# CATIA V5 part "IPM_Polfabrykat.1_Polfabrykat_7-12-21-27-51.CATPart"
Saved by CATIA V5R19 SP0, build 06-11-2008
Part number: IPM_Polfabrykat.1_Polfabrykat7-12-21-27-51
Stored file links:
  G:\Catia\CD\Ustawienia\Ustawienia\IPM_Polfabrykat.1_Polfabrykat_7-12-21-27-51.CATPart
  G:\Catia\CD\Ustawienia\Ustawienia\Polfabrykat.CATPart
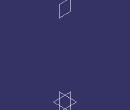
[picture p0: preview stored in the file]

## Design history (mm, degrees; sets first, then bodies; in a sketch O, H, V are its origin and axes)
Body1 (main body)
  Body2 "ImportedStock"
    Body3 "Polfabrykat"
      Solid1: linked copy from another document
    Add1: tool Body3
  Add2: tool Body2
  Body4 "Rough Turning.1"
    Plane1: stored without definition
    Sketch1 on Plane1, origin (0, 0, 38.2543), H (0, 0, 1), V (1, 0, 0)
      axis line L1 through (0, 0) direction (1, 0)
      line L2 (-0.5126, 0) -> (6.444, 4.0361)
      point P1 (-0.5126, 0)
      point P2 (6.444, 4.0361)
      line L3 (6.444, 4.0361) -> (6.6562, 4.2482)
      point P3 (6.444, 4.0361)
      point P4 (6.6562, 4.2482)
      arc A1 centre (6.3026, 4.6017) radius 0.5 from (6.6562, 4.2482) to (6.8007, 4.5582) ccw
      point P5 (6.6562, 4.2482)
      point P6 (6.8007, 4.5582)
      line L4 (6.8007, 4.5582) -> (7.5659, 13.304)
      point P7 (6.8007, 4.5582)
      point P8 (7.5659, 13.304)
      arc A2 centre (7.095, 13.3527) radius 0.4733 from (7.5659, 13.304) to (7.3556, 13.7478) ccw
      point P9 (7.5659, 13.304)
      point P10 (7.3556, 13.7478)
      line L5 (7.3556, 13.7478) -> (7.3556, 60.6354)
      point P11 (7.3556, 13.7478)
      point P12 (7.3556, 60.6354)
      arc A3 centre (6.8556, 60.6354) radius 0.5 from (7.3556, 60.6354) to (6.6056, 61.0684) ccw
      point P13 (7.3556, 60.6354)
      point P14 (6.6056, 61.0684)
      line L6 (6.6056, 61.0684) -> (-0.9974, 56.6788)
      point P15 (6.6056, 61.0684)
      point P16 (-0.9974, 56.6788)
      arc A4 centre (-0.7474, 56.2458) radius 0.5 from (-0.9974, 56.6788) to (-1.2455, 56.2894) ccw
      point P17 (-0.9974, 56.6788)
      point P18 (-1.2455, 56.2894)
      line L7 (-1.2455, 56.2894) -> (-2.0126, 47.5)
      point P19 (-1.2455, 56.2894)
      point P20 (-2.0126, 47.5)
      line L8 (-2.0126, 47.5) -> (-2.0126, 0)
      point P21 (-2.0126, 47.5)
      point P22 (-2.0126, 0)
      line L9 (-2.0126, 0) -> (-0.5126, 0)
      point P23 (-2.0126, 0)
      point P24 (-0.5126, 0)
      coincidence: P1 P24, P2 P3, P4 P5, P6 P7, P8 P9, P10 P11, P12 P13, P14 P15, P16 P17, P18 P19, P20 P21, P22 P23
    Shaft1: profile Sketch1, axis Sketch1.L1, angle 360
  Remove1: tool Body4
  Body5 "Rough Turning.2"
    Plane2: stored without definition
    Sketch2 on Plane2, origin (0, 0, 38.2543), H (0, 0, 1), V (1, 0, 0)
      axis line L1 through (0, 0) direction (1, 0)
      line L2 (0.5, 28.5858) -> (0.5, 45.5)
      point P1 (0.5, 28.5858)
      point P2 (0.5, 45.5)
      line L3 (0.5, 45.5) -> (-49.0126, 45.5)
      point P3 (0.5, 45.5)
      point P4 (-49.0126, 45.5)
      line L4 (-49.0126, 45.5) -> (-49.0126, 35.5071)
      point P5 (-49.0126, 45.5)
      point P6 (-49.0126, 35.5071)
      arc A1 centre (-48.5126, 35.5071) radius 0.5 from (-49.0126, 35.5071) to (-48.8661, 35.1536) ccw
      point P7 (-49.0126, 35.5071)
      point P8 (-48.8661, 35.1536)
      line L5 (-48.8661, 35.1536) -> (-48.859, 35.1464)
      point P9 (-48.8661, 35.1536)
      point P10 (-48.859, 35.1464)
      arc A2 centre (-48.5055, 35.5) radius 0.5 from (-48.859, 35.1464) to (-48.5055, 35) ccw
      point P11 (-48.859, 35.1464)
      point P12 (-48.5055, 35)
      line L6 (-48.5055, 35) -> (-44.0126, 35)
      point P13 (-48.5055, 35)
      point P14 (-44.0126, 35)
      line L7 (-44.0126, 35) -> (-44.0126, 30.5071)
      point P15 (-44.0126, 35)
      point P16 (-44.0126, 30.5071)
      arc A3 centre (-43.5126, 30.5071) radius 0.5 from (-44.0126, 30.5071) to (-43.8661, 30.1536) ccw
      point P17 (-44.0126, 30.5071)
      point P18 (-43.8661, 30.1536)
      line L8 (-43.8661, 30.1536) -> (-43.859, 30.1464)
      point P19 (-43.8661, 30.1536)
      point P20 (-43.859, 30.1464)
      arc A4 centre (-43.5055, 30.5) radius 0.5 from (-43.859, 30.1464) to (-43.5055, 30) ccw
      point P21 (-43.859, 30.1464)
      point P22 (-43.5055, 30)
      line L9 (-43.5055, 30) -> (-3.4268, 30)
      point P23 (-43.5055, 30)
      point P24 (-3.4268, 30)
      line L10 (-3.4268, 30) -> (-2.159, 28.7322)
      point P25 (-3.4268, 30)
      point P26 (-2.159, 28.7322)
      arc A5 centre (-1.8055, 29.0858) radius 0.5 from (-2.159, 28.7322) to (-1.8055, 28.5858) ccw
      point P27 (-2.159, 28.7322)
      point P28 (-1.8055, 28.5858)
      line L11 (-1.8055, 28.5858) -> (0.5, 28.5858)
      point P29 (-1.8055, 28.5858)
      point P30 (0.5, 28.5858)
      coincidence: P1 P30, P2 P3, P4 P5, P6 P7, P8 P9, P10 P11, P12 P13, P14 P15, P16 P17, P18 P19, P20 P21, P22 P23, P24 P25, P26 P27, P28 P29
    Shaft2: profile Sketch2, axis Sketch2.L1, angle 360
  Remove2: tool Body5
Body6 "Input Stock Body for_Groove Turning.1_21.27.56"
  Plane3 "ProfilePlane": stored without definition
  Sketch3 "Input Stock Sketch for_Groove Turning.1_21.27.56" on Plane3, origin (0, 0, 196.0027), H (0, 0, 1), V (1, 0, 0)
    line L1 (-275.7484, -45) -> (-275.7484, 45)
    line L2 (-275.7484, 45) -> (-206.761, 45)
    line L3 (-206.761, 35.5071) -> (-206.761, 45)
    frozenspline C1
    line L4 (-206.6074, 35.1464) -> (-206.6145, 35.1536)
    frozenspline C2
    line L5 (-206.2539, 35) -> (-201.761, 35)
    line L6 (-201.761, 30.5071) -> (-201.761, 35)
    frozenspline C3
    line L7 (-201.6074, 30.1464) -> (-201.6145, 30.1536)
    frozenspline C4
    line L8 (-201.2539, 30) -> (-161.1752, 30)
    line L9 (-159.9074, 28.7322) -> (-161.1752, 30)
    frozenspline C5
    line L10 (-159.761, -28.6307) -> (-159.761, 28.6307)
    frozenspline C6
    line L11 (-159.9074, -28.7322) -> (-161.1752, -30)
    line L12 (-201.2539, -30) -> (-161.1752, -30)
    frozenspline C7
    line L13 (-201.6074, -30.1464) -> (-201.6145, -30.1536)
    frozenspline C8
    line L14 (-201.761, -35) -> (-201.761, -30.5071)
    line L15 (-206.2539, -35) -> (-201.761, -35)
    frozenspline C9
    line L16 (-206.6074, -35.1464) -> (-206.6145, -35.1536)
    frozenspline C10
    line L17 (-206.761, -45) -> (-206.761, -35.5071)
    line L18 (-275.7484, -45) -> (-206.761, -45)
    line L19 (-158.261, 0) -> (-157.7484, 0.2974)
    line L20 (-157.7484, -0.2974) -> (-157.7484, 0.2974)
    line L21 (-158.261, 0) -> (-157.7484, -0.2974)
